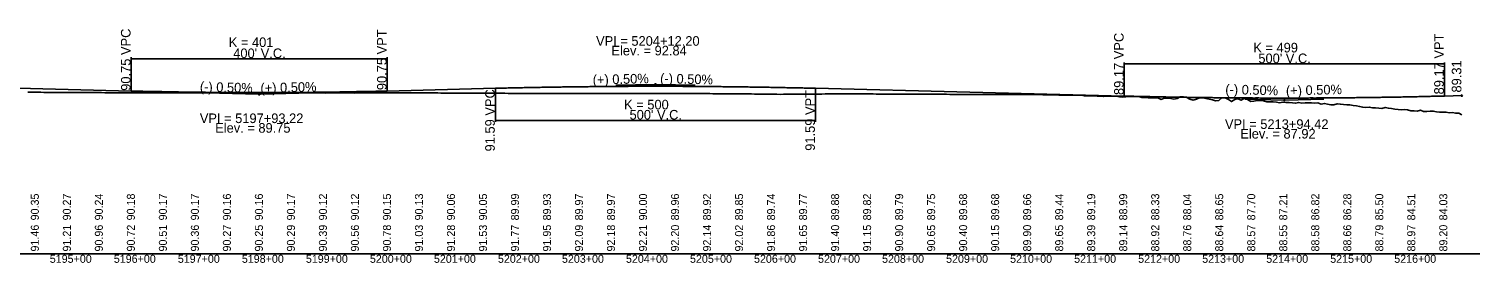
# Model space of a CAD drawing. Extents: x 2121671 to 2169879, y 557274 to 599957.
# Drawn here: x 2149002 to 2151268, y 598693 to 599058 of the extents above; entities that cross this region are included whole.
import ezdxf

# ---------------------------------------------------------------- set-up
doc = ezdxf.new("R2010")
doc.units = 0
for name, color, linetype in [('RD_DDB_GradeTX', 7, 'Continuous'), ('RD_DDB_Profile_EX', 7, 'Continuous'), ('RD_DDB_Profile_Lbl', 7, 'Continuous'), ('RD_DDB_Profile_PR', 7, 'Continuous'), ('RD_DDB_StaTX', 7, 'Continuous'), ('RD_DDB_StripGrade', 7, 'Continuous'), ('RD_DDB_VCLbl', 7, 'Continuous'), ('RD_GPK_Profile_Cell', 7, 'Continuous')]:
    doc.layers.add(name, color=color, linetype=linetype)

msp = doc.modelspace()

# ---------------------------------------------------------------- linework, layer by layer
at = {"layer": 'RD_DDB_GradeTX'}
for p, q in [((2149299.5, 598957.8), (2149360.5, 598956.2)), ((2149423.4, 598957.8), (2149362.5, 598956.2)), ((2149918.5, 598970.1), (2149979.4, 598971.6)), ((2150042.4, 598970.1), (2149981.4, 598971.6)), ((2150900.7, 598948.6), (2150961.7, 598947.1)), ((2151024.6, 598948.6), (2150963.7, 598947.1))]:
    msp.add_line(p, q, dxfattribs=at)
for centre in [(2149361.5, 598956.2), (2149980.4, 598971.7), (2151239.8, 598954), (2150962.7, 598947.1)]:
    msp.add_circle(centre, 1, dxfattribs=at)
at = {"layer": 'RD_DDB_Profile_EX'}
for points in [[(2149000.2, 598959.2), (2149005.2, 598959.2), (2149010.2, 598959.2), (2149015.2, 598959.2), (2149020.2, 598959.2), (2149025.2, 598959.1), (2149030.2, 598959.1), (2149035.2, 598959), (2149040.2, 598959), (2149045.2, 598958.9), (2149050.2, 598958.9), (2149055.2, 598958.8), (2149060.2, 598958.8), (2149065.2, 598958.8), (2149070.2, 598958.8), (2149075.2, 598958.8), (2149080.2, 598958.8), (2149085.2, 598958.8), (2149090.2, 598958.8), (2149095.2, 598958.8), (2149100.2, 598958.8), (2149105.2, 598958.8), (2149110.2, 598958.7), (2149115.2, 598958.7), (2149120.2, 598958.6), (2149125.2, 598958.6), (2149130.2, 598958.6), (2149135.2, 598958.5), (2149140.2, 598958.5), (2149145.2, 598958.5), (2149150.2, 598958.4), (2149155.2, 598958.4), (2149160.2, 598958.4), (2149165.2, 598958.4), (2149170.2, 598958.3), (2149175.2, 598958.3), (2149180.2, 598958.3), (2149185.2, 598958.3), (2149190.2, 598958.3), (2149195.2, 598958.3), (2149200.2, 598958.3), (2149205.2, 598958.3), (2149210.2, 598958.3), (2149215.2, 598958.3)], [(2149215.2, 598958.3), (2149220.2, 598958.3), (2149225.2, 598958.3), (2149230.2, 598958.3), (2149235.2, 598958.3), (2149240.2, 598958.4), (2149245.2, 598958.4), (2149250.2, 598958.4), (2149255.2, 598958.4), (2149260.2, 598958.3), (2149265.2, 598958.3), (2149270.2, 598958.3), (2149275.2, 598958.3), (2149280.2, 598958.3), (2149285.2, 598958.3), (2149290.2, 598958.3), (2149295.2, 598958.3), (2149300.2, 598958.3), (2149305.2, 598958.3), (2149310.2, 598958.3), (2149315.2, 598958.3), (2149320.2, 598958.3), (2149325.2, 598958.2), (2149330.2, 598958.2), (2149335.2, 598958.2), (2149340.2, 598958.3), (2149345.2, 598958.3), (2149350.2, 598958.3), (2149355.2, 598958.3), (2149360.2, 598958.3), (2149365.2, 598958.3), (2149370.2, 598958.3), (2149375.2, 598958.3), (2149380.2, 598958.3), (2149385.2, 598958.3), (2149390.2, 598958.3), (2149395.2, 598958.3), (2149400.2, 598958.3), (2149405.2, 598958.3), (2149410.2, 598958.3), (2149415.2, 598958.3), (2149420.2, 598958.3), (2149425.2, 598958.2), (2149430.2, 598958.2), (2149435.2, 598958.2), (2149440.2, 598958.1), (2149445.2, 598958.1), (2149450.2, 598958.1), (2149455.2, 598958.1), (2149460.2, 598958.1), (2149465.2, 598958), (2149470.2, 598958.1), (2149475.2, 598958.1), (2149480.2, 598958.1), (2149485.2, 598958.1), (2149490.2, 598958.1), (2149495.2, 598958.1), (2149500.2, 598958.1), (2149505.2, 598958.1), (2149510.2, 598958), (2149515.2, 598958.1), (2149520.2, 598958.1), (2149525.2, 598958.1), (2149530.2, 598958.1), (2149535.2, 598958.1), (2149540.2, 598958.1), (2149545.2, 598958.1), (2149550.2, 598958.1), (2149555.2, 598958.2), (2149560.2, 598958.2), (2149565.2, 598958.2), (2149570.2, 598958.2), (2149575.2, 598958.2), (2149580.2, 598958.2), (2149585.2, 598958.2), (2149590.2, 598958.2), (2149595.2, 598958.1), (2149600.2, 598958.1), (2149605.2, 598958.1), (2149610.2, 598958.1), (2149615.2, 598958.1), (2149620.2, 598958.1), (2149625.2, 598958.1), (2149630.2, 598958.1), (2149635.2, 598958.1), (2149640.2, 598958.1), (2149645.2, 598958), (2149650.2, 598958), (2149655.2, 598957.9), (2149660.2, 598957.9), (2149665.2, 598957.9), (2149670.2, 598957.7), (2149675.2, 598957.7), (2149680.2, 598957.6), (2149685.2, 598957.6), (2149690.2, 598957.6), (2149695.2, 598957.7), (2149700.2, 598957.7), (2149705.2, 598957.6), (2149710.2, 598957.8), (2149715.2, 598957.8)], [(2149715.2, 598957.8), (2149720.2, 598957.7), (2149725.2, 598957.7), (2149730.2, 598957.7), (2149735.2, 598957.7), (2149740.2, 598957.7), (2149745.2, 598957.6), (2149750.2, 598957.5), (2149755.2, 598957.5), (2149760.2, 598957.5), (2149765.2, 598957.4), (2149770.2, 598957.4), (2149775.2, 598957.5), (2149780.2, 598957.5), (2149785.2, 598957.4), (2149790.2, 598957.3), (2149795.2, 598957.2), (2149800.2, 598957.2), (2149805.2, 598957.2), (2149810.2, 598957.2), (2149815.2, 598957.1), (2149820.2, 598957.1), (2149825.2, 598957.1), (2149830.2, 598957.1), (2149835.2, 598957.1), (2149840.2, 598957.1), (2149845.2, 598957.1), (2149850.2, 598957.1), (2149855.2, 598957.1), (2149860.2, 598957.3), (2149865.2, 598957.3), (2149870.2, 598957.3), (2149875.2, 598957.3), (2149880.2, 598957.4), (2149885.2, 598957.4), (2149890.2, 598957.5), (2149895.2, 598957.5), (2149900.2, 598957.4), (2149905.2, 598957.4), (2149910.2, 598957.4), (2149915.2, 598957.3), (2149920.2, 598957.3), (2149925.2, 598957.3), (2149930.2, 598957.2), (2149935.2, 598957.4), (2149940.2, 598957.5), (2149945.2, 598957.5), (2149950.2, 598957.5), (2149955.2, 598957.5), (2149960.2, 598957.5), (2149965.2, 598957.5), (2149970.2, 598957.4), (2149975.2, 598957.5), (2149980.2, 598957.4), (2149985.2, 598957.4), (2149990.2, 598957.4), (2149995.2, 598957.4), (2150000.2, 598957.4), (2150005.2, 598957.4), (2150010.2, 598957.3), (2150015.2, 598957.2), (2150020.2, 598957.3), (2150025.2, 598957.3), (2150030.2, 598957.3), (2150035.2, 598957.3), (2150040.2, 598957.3), (2150045.2, 598957.3), (2150050.2, 598957.4), (2150055.2, 598957.4), (2150060.2, 598957.2), (2150065.2, 598957.1), (2150070.2, 598957), (2150075.2, 598957), (2150080.2, 598957), (2150085.2, 598957), (2150090.2, 598956.9), (2150095.2, 598956.9), (2150100.2, 598956.9), (2150105.2, 598956.8), (2150110.2, 598956.8), (2150115.2, 598956.7), (2150120.2, 598956.7), (2150125.2, 598956.6), (2150130.2, 598956.6), (2150135.2, 598956.5), (2150140.2, 598956.2), (2150145.2, 598956.2), (2150150.2, 598956.2), (2150155.2, 598956.2), (2150160.2, 598956.2), (2150165.2, 598956.2), (2150170.2, 598956.2), (2150175.2, 598956), (2150180.2, 598956.2), (2150185.2, 598956.3), (2150190.2, 598956.3), (2150195.2, 598956.3), (2150200.2, 598956.2), (2150205.2, 598956.3), (2150210.2, 598956.4), (2150215.2, 598956.3)], [(2150215.2, 598956.3), (2150220.2, 598956.3), (2150225.2, 598956.3), (2150230.2, 598956.2), (2150235.2, 598956.2), (2150240.2, 598956.5), (2150245.2, 598956.6), (2150250.2, 598956.7), (2150255.2, 598956.7), (2150260.2, 598956.8), (2150265.2, 598956.9), (2150270.2, 598956.9), (2150275.2, 598956.9), (2150280.2, 598956.8), (2150285.2, 598956.8), (2150290.2, 598956.8), (2150295.2, 598956.7), (2150300.2, 598956.7), (2150305.2, 598956.6), (2150310.2, 598956.6), (2150315.2, 598956.6), (2150320.2, 598956.6), (2150325.2, 598956.5), (2150330.2, 598956.5), (2150335.2, 598956.4), (2150340.2, 598956.4), (2150345.2, 598956.4), (2150350.2, 598956.4), (2150355.2, 598956.4), (2150360.2, 598956.4), (2150365.2, 598956.4), (2150370.2, 598956.4), (2150375.2, 598956.4), (2150380.2, 598956.4), (2150385.2, 598956.4), (2150390.2, 598956.4), (2150395.2, 598956.4), (2150400.2, 598956.4), (2150405.2, 598956.4), (2150410.2, 598956.3), (2150415.2, 598956.3), (2150420.2, 598956.2), (2150425.2, 598956.2), (2150430.2, 598956.1), (2150435.2, 598956.1), (2150440.2, 598956), (2150445.2, 598956), (2150450.2, 598955.9), (2150455.2, 598955.9), (2150460.2, 598955.9), (2150465.2, 598955.9), (2150470.2, 598955.9), (2150475.2, 598955.9), (2150480.2, 598955.9), (2150485.2, 598955.9), (2150490.2, 598955.9), (2150495.2, 598955.9), (2150500.2, 598955.9), (2150505.2, 598955.9), (2150510.2, 598955.9), (2150515.2, 598955.9), (2150520.2, 598955.8), (2150525.2, 598955.8), (2150530.2, 598955.8), (2150535.2, 598955.8), (2150540.2, 598955.8), (2150545.2, 598955.9), (2150550.2, 598955.9), (2150555.2, 598955.9), (2150560.2, 598955.9), (2150565.2, 598955.8), (2150570.2, 598955.7), (2150575.2, 598955.6), (2150580.2, 598955.5), (2150585.2, 598955.3), (2150590.2, 598955.2), (2150595.2, 598955.2), (2150600.2, 598955.1), (2150605.2, 598955), (2150610.2, 598954.9), (2150615.2, 598954.8), (2150620.2, 598954.6), (2150625.2, 598954.5), (2150630.2, 598954.5), (2150635.2, 598954.5), (2150640.2, 598954.5), (2150645.2, 598954.5), (2150650.2, 598953.9), (2150655.2, 598953.6), (2150660.2, 598953.5), (2150665.2, 598953.5), (2150670.2, 598953.4), (2150675.2, 598953.3), (2150680.2, 598952.4), (2150685.2, 598953.3), (2150690.2, 598953.4), (2150695.2, 598953.2), (2150700.2, 598953), (2150705.2, 598952.2), (2150710.2, 598951.6), (2150715.2, 598952.1)], [(2150715.2, 598952.1), (2150720.2, 598952.7), (2150725.2, 598952.6), (2150730.2, 598952.5), (2150735.2, 598952.4), (2150740.2, 598951.1), (2150745.2, 598950.9), (2150750.2, 598950.8), (2150755.2, 598950.7), (2150760.2, 598950.6), (2150765.2, 598950.4), (2150770.2, 598948.2), (2150775.2, 598950.2), (2150780.2, 598949.8), (2150785.2, 598949.6), (2150790.2, 598948.5), (2150795.2, 598949.3), (2150800.2, 598952), (2150805.2, 598952), (2150810.2, 598951), (2150815.2, 598948.7), (2150820.2, 598947), (2150825.2, 598948.4), (2150830.2, 598950.8), (2150835.2, 598950.3), (2150840.2, 598949.5), (2150845.2, 598948.4), (2150850.2, 598947.2), (2150855.2, 598945.8), (2150860.2, 598946.5), (2150865.2, 598950.8), (2150870.2, 598950.6), (2150875.2, 598948.1), (2150880.2, 598944.7), (2150885.2, 598948), (2150890.2, 598948.8), (2150895.2, 598946.7), (2150900.2, 598950.2), (2150905.2, 598948), (2150910.2, 598944.8), (2150915.2, 598945.4), (2150920.2, 598946.3), (2150925.2, 598946.2), (2150930.2, 598945.8), (2150935.2, 598944.4), (2150940.2, 598944.1), (2150945.2, 598944.4), (2150950.2, 598943.8), (2150955.2, 598942.9), (2150960.2, 598943.8), (2150965.2, 598943.5), (2150970.2, 598943.5), (2150975.2, 598942.9), (2150980.2, 598942.2), (2150985.2, 598943.3), (2150990.2, 598942.4), (2150995.2, 598942.8), (2151000.2, 598942.8), (2151005.2, 598943), (2151010.2, 598942.5), (2151015.2, 598942.7), (2151020.2, 598940.9), (2151025.2, 598941.9), (2151030.2, 598940.6), (2151035.2, 598939.7), (2151040.2, 598939.7), (2151045.2, 598941.4), (2151050.2, 598940.5), (2151055.2, 598940), (2151060.2, 598939.6), (2151065.2, 598939.5), (2151070.2, 598938.4), (2151075.2, 598938.1), (2151080.2, 598937.3), (2151085.2, 598935.8), (2151090.2, 598935.4), (2151095.2, 598936.2), (2151100.2, 598935), (2151105.2, 598935), (2151110.2, 598934.3), (2151115.2, 598934.1), (2151120.2, 598935.5), (2151125.2, 598934.3), (2151130.2, 598933.7), (2151135.2, 598933.1), (2151140.2, 598932.4), (2151145.2, 598932), (2151150.2, 598932.5), (2151155.2, 598932.1), (2151160.2, 598930.1), (2151165.2, 598930.1), (2151170.2, 598929.9), (2151175.2, 598931.3), (2151180.2, 598929.4), (2151185.2, 598929.3), (2151190.2, 598929.6), (2151195.2, 598929.8), (2151200.2, 598928.8), (2151205.2, 598928.4), (2151210.2, 598928), (2151215.2, 598928.4)], [(2151215.2, 598928.4), (2151220.2, 598927.1), (2151225.2, 598927.6), (2151230.2, 598926.7), (2151235.2, 598926.4), (2151239.8, 598924.1)]]:
    msp.add_lwpolyline(points, dxfattribs=at)
at = {"layer": 'RD_DDB_Profile_PR'}
for p, q in [((2148964.7, 598966.1), (2149161.5, 598961.2)), ((2149561.5, 598961.2), (2149730.4, 598965.4)), ((2150230.4, 598965.4), (2150712.7, 598953.3)), ((2151212.7, 598953.3), (2151239.8, 598954))]:
    msp.add_line(p, q, dxfattribs=at)
for points in [[(2149161.5, 598961.2), (2149169.5, 598961), (2149177.5, 598960.8), (2149185.5, 598960.6), (2149193.5, 598960.5), (2149201.5, 598960.3), (2149209.5, 598960.2), (2149217.5, 598960), (2149225.5, 598959.9), (2149233.5, 598959.7), (2149241.5, 598959.6), (2149249.5, 598959.5), (2149257.5, 598959.4), (2149265.5, 598959.3), (2149273.5, 598959.2), (2149281.5, 598959.1), (2149289.5, 598959), (2149297.5, 598959), (2149305.5, 598958.9), (2149313.5, 598958.9), (2149321.5, 598958.8), (2149329.5, 598958.8), (2149337.5, 598958.8), (2149345.5, 598958.7), (2149353.5, 598958.7), (2149361.5, 598958.7), (2149369.5, 598958.7), (2149377.5, 598958.7), (2149385.5, 598958.8), (2149393.5, 598958.8), (2149401.5, 598958.8), (2149409.5, 598958.9), (2149417.5, 598958.9), (2149425.5, 598959), (2149433.5, 598959), (2149441.5, 598959.1), (2149449.5, 598959.2), (2149457.5, 598959.3), (2149465.5, 598959.4), (2149473.5, 598959.5), (2149481.5, 598959.6), (2149489.5, 598959.7), (2149497.5, 598959.9), (2149505.5, 598960), (2149513.5, 598960.2), (2149521.5, 598960.3), (2149529.5, 598960.5), (2149537.5, 598960.6), (2149545.5, 598960.8), (2149553.5, 598961), (2149561.5, 598961.2)], [(2149730.4, 598965.4), (2149740.4, 598965.7), (2149750.4, 598965.9), (2149760.4, 598966.1), (2149770.4, 598966.3), (2149780.4, 598966.6), (2149790.4, 598966.7), (2149800.4, 598966.9), (2149810.4, 598967.1), (2149820.4, 598967.3), (2149830.4, 598967.4), (2149840.4, 598967.6), (2149850.4, 598967.7), (2149860.4, 598967.8), (2149870.4, 598967.9), (2149880.4, 598968), (2149890.4, 598968.1), (2149900.4, 598968.2), (2149910.4, 598968.3), (2149920.4, 598968.4), (2149930.4, 598968.4), (2149940.4, 598968.5), (2149950.4, 598968.5), (2149960.4, 598968.5), (2149970.4, 598968.5), (2149980.4, 598968.5), (2149990.4, 598968.5), (2150000.4, 598968.5), (2150010.4, 598968.5), (2150020.4, 598968.5), (2150030.4, 598968.4), (2150040.4, 598968.4), (2150050.4, 598968.3), (2150060.4, 598968.2), (2150070.4, 598968.1), (2150080.4, 598968), (2150090.4, 598967.9), (2150100.4, 598967.8), (2150110.4, 598967.7), (2150120.4, 598967.6), (2150130.4, 598967.4), (2150140.4, 598967.3), (2150150.4, 598967.1), (2150160.4, 598966.9), (2150170.4, 598966.7), (2150180.4, 598966.5), (2150190.4, 598966.3), (2150200.4, 598966.1), (2150210.4, 598965.9), (2150220.4, 598965.7), (2150230.4, 598965.4)], [(2150712.7, 598953.3), (2150722.7, 598953.1), (2150732.7, 598952.8), (2150742.7, 598952.6), (2150752.7, 598952.4), (2150762.7, 598952.2), (2150772.7, 598952), (2150782.7, 598951.8), (2150792.7, 598951.6), (2150802.7, 598951.5), (2150812.7, 598951.3), (2150822.7, 598951.2), (2150832.7, 598951), (2150842.7, 598950.9), (2150852.7, 598950.8), (2150862.7, 598950.7), (2150872.7, 598950.6), (2150882.7, 598950.5), (2150892.7, 598950.4), (2150902.7, 598950.4), (2150912.7, 598950.3), (2150922.7, 598950.3), (2150932.7, 598950.2), (2150942.7, 598950.2), (2150952.7, 598950.2), (2150962.7, 598950.2), (2150972.7, 598950.2), (2150982.7, 598950.2), (2150992.7, 598950.2), (2151002.7, 598950.3), (2151012.7, 598950.3), (2151022.7, 598950.4), (2151032.7, 598950.4), (2151042.7, 598950.5), (2151052.7, 598950.6), (2151062.7, 598950.7), (2151072.7, 598950.8), (2151082.7, 598950.9), (2151092.7, 598951.1), (2151102.7, 598951.2), (2151112.7, 598951.3), (2151122.7, 598951.5), (2151132.7, 598951.7), (2151142.7, 598951.8), (2151152.7, 598952), (2151162.7, 598952.2), (2151172.7, 598952.4), (2151182.7, 598952.6), (2151192.7, 598952.9), (2151202.7, 598953.1), (2151212.7, 598953.3)]]:
    msp.add_spline(points, degree=3, dxfattribs=at)
at = {"layer": 'RD_DDB_VCLbl'}
for p, q in [((2149161.5, 599013.7), (2149161.5, 598961.2)), ((2149161.5, 599011.2), (2149561.5, 599011.2)), ((2149561.5, 599013.7), (2149561.5, 598961.2)), ((2150712.7, 599005.8), (2150712.7, 598953.3)), ((2150712.7, 599003.3), (2151212.7, 599003.3)), ((2151212.7, 599005.8), (2151212.7, 598953.3)), ((2149730.4, 598912.9), (2149730.4, 598965.4)), ((2150230.4, 598912.9), (2150230.4, 598965.4)), ((2149730.4, 598915.4), (2150230.4, 598915.4))]:
    msp.add_line(p, q, dxfattribs=at)
at = {"layer": 'RD_GPK_Profile_Cell'}
msp.add_line((2146668.2, 598707.5), (2151268.2, 598707.5), dxfattribs=at)
msp.add_line((2146668.2, 598707.5), (2151268.2, 598707.5), dxfattribs=at)
msp.add_line((2146668.2, 598707.5), (2151268.2, 598707.5), dxfattribs=at)

# ---------------------------------------------------------------- texts
at = {"layer": 'RD_DDB_GradeTX'}
for s, rotation, p in [('(+) 0.50%', 1.4298, (2149882.5, 598971.2)), ('(-) 0.50%', 358.5653, (2149987.5, 598973.5)), ('(-) 0.50%', 358.5698, (2149268.6, 598960.5)), ('(+) 0.50%', 1.4298, (2149363.5, 598958.3)), ('(-) 0.50%', 358.5653, (2150870.3, 598956.5)), ('(+) 0.50%', 1.4367, (2150965.3, 598954.2))]:
    msp.add_text(s, height=15, rotation=rotation, dxfattribs=at).set_placement(p)
at = {"layer": 'RD_DDB_Profile_Lbl'}
for s, p in [('VPI = 5204+12.20', (2149887.6, 599031.7)), ('Elev. = 92.84', (2149911.6, 599016.7)), ('VPI = 5197+93.22', (2149268.7, 598911.2)), ('Elev. = 89.75', (2149292.7, 598896.2)), ('VPI = 5213+94.42', (2150869.9, 598902.1)), ('Elev. = 87.92', (2150893.9, 598887.1))]:
    msp.add_text(s, height=15, dxfattribs=at).set_placement(p)
msp.add_text('89.31', height=15, rotation=90, dxfattribs=at).set_placement((2151239.2, 598958.8))
at = {"layer": 'RD_DDB_StaTX'}
for s, p in [('5195+00', (2149034.3, 598693.4)), ('5196+00', (2149134.3, 598693.4)), ('5197+00', (2149234.3, 598693.4)), ('5198+00', (2149334.3, 598693.4)), ('5199+00', (2149434.3, 598693.4)), ('5200+00', (2149534.3, 598693.4)), ('5201+00', (2149634.3, 598693.4)), ('5202+00', (2149734.3, 598693.4)), ('5203+00', (2149834.3, 598693.4)), ('5204+00', (2149934.3, 598693.4)), ('5205+00', (2150034.3, 598693.4)), ('5206+00', (2150134.3, 598693.4)), ('5207+00', (2150234.3, 598693.4)), ('5208+00', (2150334.3, 598693.4)), ('5209+00', (2150434.3, 598693.4)), ('5210+00', (2150534.3, 598693.4)), ('5211+00', (2150634.3, 598693.4)), ('5212+00', (2150734.3, 598693.4)), ('5213+00', (2150834.3, 598693.4)), ('5214+00', (2150934.3, 598693.4)), ('5215+00', (2151034.3, 598693.4)), ('5216+00', (2151134.3, 598693.4))]:
    msp.add_text(s, height=12.5, dxfattribs=at).set_placement(p)
at = {"layer": 'RD_DDB_StripGrade'}
for s, height, p in [('90.75 VPC', 15, (2149160.5, 598961.5)), ('90.75 VPT', 15, (2149560.5, 598962.5)), ('89.17 VPC', 15, (2150711.7, 598954.9)), ('89.17 VPT', 15, (2151211.7, 598955.9)), ('91.59 VPC', 15, (2149729.4, 598867)), ('91.59 VPT', 15, (2150229.4, 598868)), ('90.35', 12.5, (2149017.2, 598759.5)), ('90.27', 12.5, (2149067.2, 598759.5)), ('90.24', 12.5, (2149117.2, 598759.5)), ('90.18', 12.5, (2149167.2, 598759.5)), ('90.17', 12.5, (2149217.2, 598759.5)), ('90.17', 12.5, (2149267.2, 598759.5)), ('90.16', 12.5, (2149317.2, 598759.5)), ('90.16', 12.5, (2149367.2, 598759.5)), ('90.17', 12.5, (2149417.2, 598759.5)), ('90.12', 12.5, (2149467.2, 598759.5)), ('90.12', 12.5, (2149517.2, 598759.5)), ('90.15', 12.5, (2149567.2, 598759.5)), ('90.13', 12.5, (2149617.2, 598759.5)), ('90.06', 12.5, (2149667.2, 598759.5)), ('90.05', 12.5, (2149717.2, 598759.5)), ('89.99', 12.5, (2149767.2, 598759.5)), ('89.93', 12.5, (2149817.2, 598759.5)), ('89.97', 12.5, (2149867.2, 598759.5)), ('89.97', 12.5, (2149917.2, 598759.5)), ('90.00', 12.5, (2149967.2, 598759.5)), ('89.96', 12.5, (2150017.2, 598759.5)), ('89.92', 12.5, (2150067.2, 598759.5)), ('89.85', 12.5, (2150117.2, 598759.5)), ('89.74', 12.5, (2150167.2, 598759.5)), ('89.77', 12.5, (2150217.2, 598759.5)), ('89.88', 12.5, (2150267.2, 598759.5)), ('89.82', 12.5, (2150317.2, 598759.5)), ('89.79', 12.5, (2150367.2, 598759.5)), ('89.75', 12.5, (2150417.2, 598759.5)), ('89.68', 12.5, (2150467.2, 598759.5)), ('89.68', 12.5, (2150517.2, 598759.5)), ('89.66', 12.5, (2150567.2, 598759.5)), ('89.44', 12.5, (2150617.2, 598759.5)), ('89.19', 12.5, (2150667.2, 598759.5)), ('88.99', 12.5, (2150717.2, 598759.5)), ('88.33', 12.5, (2150767.2, 598759.5)), ('88.04', 12.5, (2150817.2, 598759.5)), ('88.65', 12.5, (2150867.2, 598759.5)), ('87.70', 12.5, (2150917.2, 598759.5)), ('87.21', 12.5, (2150967.2, 598759.5)), ('86.82', 12.5, (2151017.2, 598759.5)), ('86.28', 12.5, (2151067.2, 598759.5)), ('85.50', 12.5, (2151117.2, 598759.5)), ('84.51', 12.5, (2151167.2, 598759.5)), ('84.03', 12.5, (2151217.2, 598759.5)), ('91.46', 12.5, (2149017.2, 598711)), ('91.21', 12.5, (2149067.2, 598711)), ('90.96', 12.5, (2149117.2, 598711)), ('90.72', 12.5, (2149167.2, 598711)), ('90.51', 12.5, (2149217.2, 598711)), ('90.36', 12.5, (2149267.2, 598711)), ('90.27', 12.5, (2149317.2, 598711)), ('90.25', 12.5, (2149367.2, 598711)), ('90.29', 12.5, (2149417.2, 598711)), ('90.39', 12.5, (2149467.2, 598711)), ('90.56', 12.5, (2149517.2, 598711)), ('90.78', 12.5, (2149567.2, 598711)), ('91.03', 12.5, (2149617.2, 598711)), ('91.28', 12.5, (2149667.2, 598711)), ('91.53', 12.5, (2149717.2, 598711)), ('91.77', 12.5, (2149767.2, 598711)), ('91.95', 12.5, (2149817.2, 598711)), ('92.09', 12.5, (2149867.2, 598711)), ('92.18', 12.5, (2149917.2, 598711)), ('92.21', 12.5, (2149967.2, 598711)), ('92.20', 12.5, (2150017.2, 598711)), ('92.14', 12.5, (2150067.2, 598711)), ('92.02', 12.5, (2150117.2, 598711)), ('91.86', 12.5, (2150167.2, 598711)), ('91.65', 12.5, (2150217.2, 598711)), ('91.40', 12.5, (2150267.2, 598711)), ('91.15', 12.5, (2150317.2, 598711)), ('90.90', 12.5, (2150367.2, 598711)), ('90.65', 12.5, (2150417.2, 598711)), ('90.40', 12.5, (2150467.2, 598711)), ('90.15', 12.5, (2150517.2, 598711)), ('89.90', 12.5, (2150567.2, 598711)), ('89.65', 12.5, (2150617.2, 598711)), ('89.39', 12.5, (2150667.2, 598711)), ('89.14', 12.5, (2150717.2, 598711)), ('88.92', 12.5, (2150767.2, 598711)), ('88.76', 12.5, (2150817.2, 598711)), ('88.64', 12.5, (2150867.2, 598711)), ('88.57', 12.5, (2150917.2, 598711)), ('88.55', 12.5, (2150967.2, 598711)), ('88.58', 12.5, (2151017.2, 598711)), ('88.66', 12.5, (2151067.2, 598711)), ('88.79', 12.5, (2151117.2, 598711)), ('88.97', 12.5, (2151167.2, 598711)), ('89.20', 12.5, (2151217.2, 598711))]:
    msp.add_text(s, height=height, rotation=90, dxfattribs=at).set_placement(p)
at = {"layer": 'RD_DDB_VCLbl'}
for s, p in [('K = 401', (2149313.9, 599029.7)), ("400' V.C.", (2149320.9, 599012.5)), ('K = 499', (2150914.2, 599021.3)), ("500' V.C.", (2150922.1, 599004.6)), ('K = 500', (2149931.4, 598932.5)), ("500' V.C.", (2149939.9, 598916.7))]:
    msp.add_text(s, height=15, dxfattribs=at).set_placement(p)

doc.saveas('drawing.dxf')
